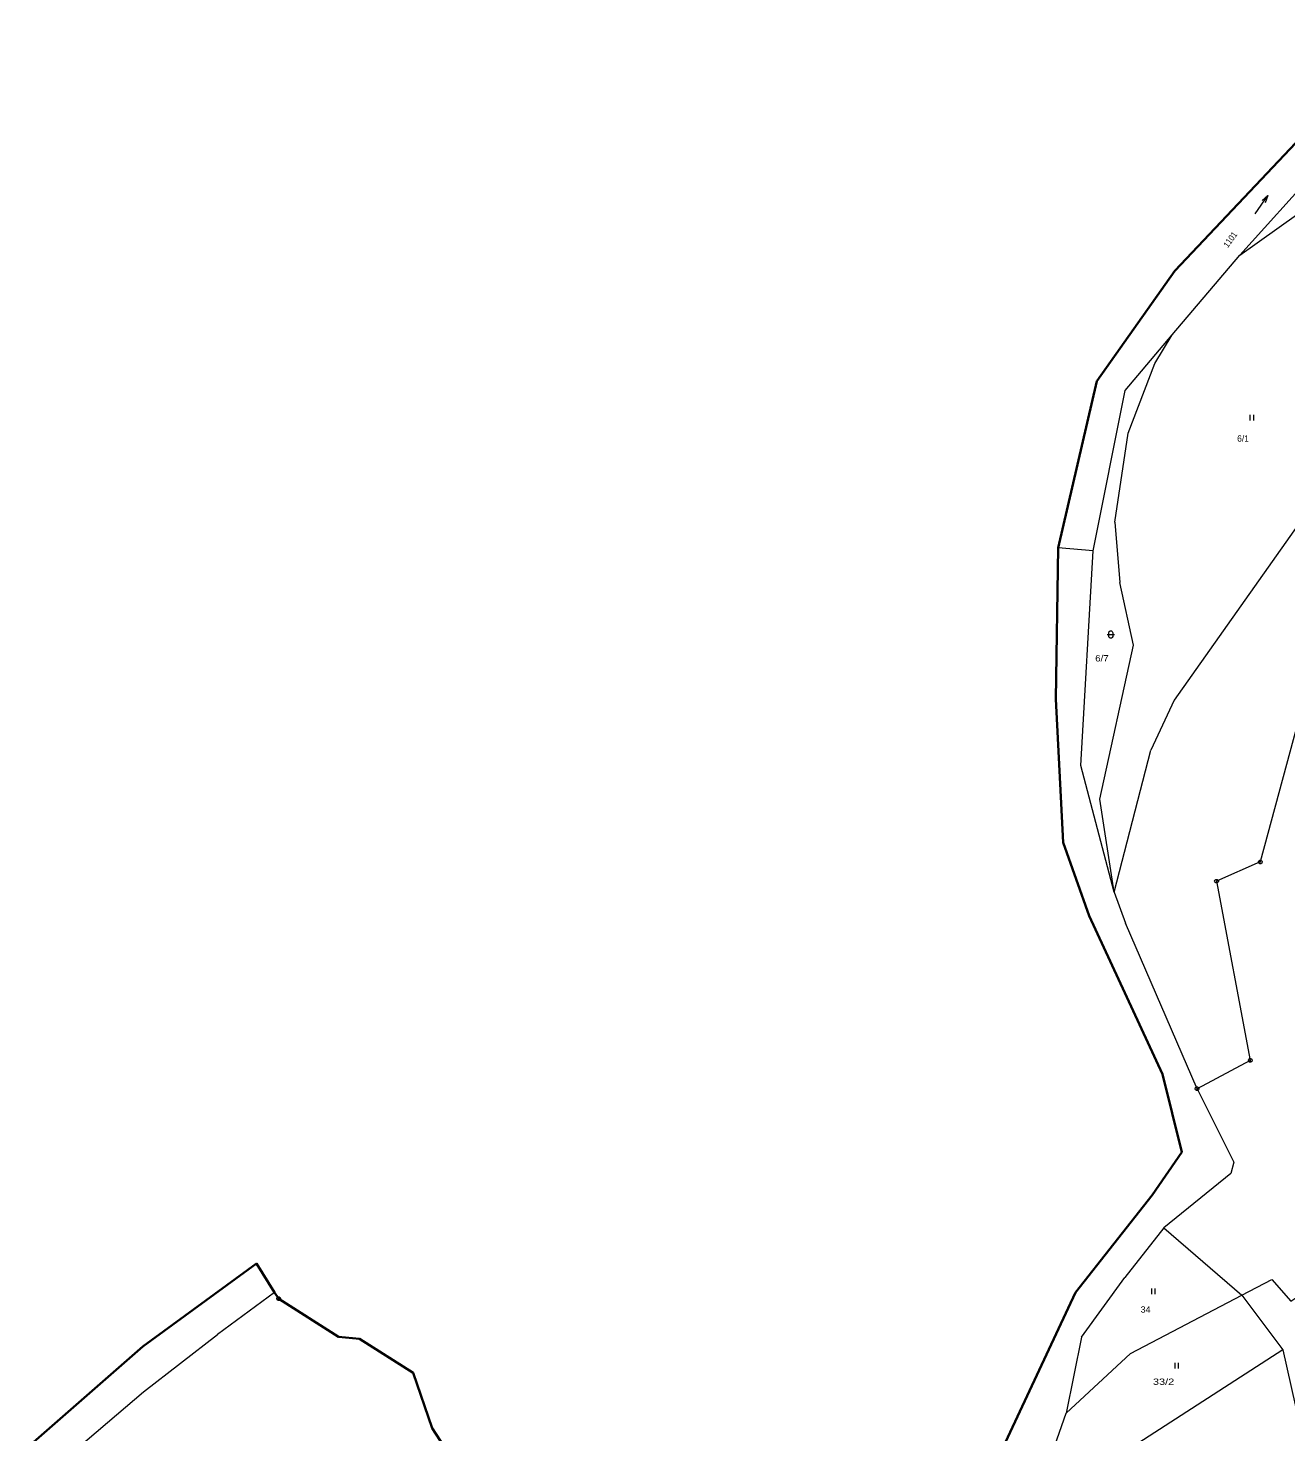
# Model space of a CAD drawing. Extents: x -687390 to -684106, y -954833 to -951648.
# Drawn here: x -687182.1 to -686842.5, y -952373.7 to -951994.7 of the extents above; entities that cross this region are included whole.
import ezdxf

# ---------------------------------------------------------------- set-up
doc = ezdxf.new("R2010")
doc.units = 0
doc.header["$LTSCALE"] = 0.68
for name, color, linetype, lineweight in [('1', 7, 'Continuous', 13), ('3', 7, 'Continuous', 13), ('8', 7, 'Continuous', 13)]:
    doc.layers.add(name, color=color, linetype=linetype, lineweight=lineweight)
doc.layers.add('2', color=7, linetype='Continuous')

msp = doc.modelspace()

# ---------------------------------------------------------------- linework, layer by layer
at = {"layer": '1', "lineweight": 35}
for p, q in [((-686872.53, -952060.23), (-686810.58, -951994.73)), ((-686893.62, -952090.01), (-686872.53, -952060.23)), ((-686904.01, -952134.99), (-686893.62, -952090.01)), ((-686904.01, -952134.99), (-686904.64, -952175.85)), ((-686902.67, -952214.58), (-686904.64, -952175.85)), ((-687098.29, -952347.95), (-687114.45, -952337.69)), ((-687151.09, -952350.57), (-687182.11, -952377.71))]:
    msp.add_line(p, q, dxfattribs=at)
at = {"layer": '1'}
for p, q in [((-686854.94, -952056.03), (-686813.73, -952010.22)), ((-686873.23, -952077.54), (-686854.94, -952056.03)), ((-686888.74, -952128.08), (-686887.36, -952144.36)), ((-686894.58, -952135.87), (-686904.01, -952134.99)), ((-686883.66, -952161.28), (-686887.36, -952144.36)), ((-686888.93, -952227.94), (-686879.03, -952189.6)), ((-686888.93, -952227.94), (-686885.86, -952236.37)), ((-686866.54, -952281.02), (-686885.86, -952236.37)), ((-686875.46, -952318.53), (-686885.99, -952332.01)), ((-686897.74, -952348.12), (-686885.99, -952332.01)), ((-687115.6, -952335.99), (-687130.95, -952347.37)), ((-686884.52, -952352.47), (-686854.46, -952336.7)), ((-687150.92, -952362.86), (-687130.95, -952347.37)), ((-686897.74, -952348.12), (-686901.87, -952368.61)), ((-686843.35, -952351.48), (-686834.2, -952392.4)), ((-686901.87, -952368.61), (-686884.52, -952352.47)), ((-687174.29, -952382.64), (-687150.92, -952362.86))]:
    msp.add_line(p, q, dxfattribs=at)
for points in [[(-686854.94, -952056.03), (-686814.36, -952027.14), (-686800.46, -951995.35)], [(-686888.93, -952227.94), (-686897.92, -952193.73), (-686894.58, -952135.87), (-686885.97, -952092.52), (-686873.23, -952077.54)], [(-686888.74, -952128.08), (-686885.15, -952104.04), (-686877.93, -952085.31), (-686873.23, -952077.54)], [(-686798.99, -952084.75), (-686803.69, -952093.23), (-686810.2, -952100.56), (-686819.98, -952104.32), (-686828.22, -952113.25), (-686872.69, -952176.15), (-686879.03, -952189.6)], [(-686791.07, -952140.62), (-686839.43, -952182.55), (-686849.46, -952219.82), (-686861.27, -952225.02), (-686852.17, -952273.36), (-686866.54, -952281.02)], [(-686888.93, -952227.94), (-686892.78, -952202.83), (-686883.66, -952161.28)], [(-686866.54, -952281.02), (-686856.6, -952300.81), (-686857.44, -952303.87), (-686875.46, -952318.53), (-686854.46, -952336.7), (-686846.31, -952332.52), (-686841.22, -952338.37), (-686831.5, -952331.87), (-686827.68, -952342.74), (-686772.24, -952340.34), (-686749.44, -952344.82), (-686720.16, -952342.03), (-686723.22, -952370.73)], [(-686854.46, -952336.7), (-686843.35, -952351.48), (-686911.22, -952395.33), (-686901.87, -952368.61)]]:
    msp.add_lwpolyline(points, dxfattribs=at)
at = {"layer": '1', "lineweight": 35}
for points in [[(-686938.29, -952406.07), (-686927.39, -952396.02), (-686899.38, -952336.06), (-686889.03, -952322.89), (-686878.68, -952309.72), (-686870.68, -952298.15), (-686875.89, -952277.07), (-686895.7, -952234.39), (-686902.67, -952214.58)], [(-687151.09, -952350.57), (-687120.48, -952328.22), (-687115.6, -952335.99), (-687114.45, -952337.69)], [(-687098.29, -952347.95), (-687092.6, -952348.56), (-687078.11, -952357.72), (-687073.06, -952372.61), (-687064.2, -952386.23), (-687053.17, -952390.55), (-687043.01, -952392.96)]]:
    msp.add_lwpolyline(points, dxfattribs=at)
at = {"layer": '3'}
for p, q in [((-686850.811, -952044.898), (-686847.429, -952039.942)), ((-686852.24, -952099.12), (-686852.24, -952100.62)), ((-686851.24, -952100.62), (-686851.24, -952099.12)), ((-686878.87, -952334.95), (-686878.87, -952336.45)), ((-686877.87, -952336.45), (-686877.87, -952334.95)), ((-686872.55, -952355.03), (-686872.55, -952356.53)), ((-686871.55, -952356.53), (-686871.55, -952355.03))]:
    msp.add_line(p, q, dxfattribs=at)
for points in [[(-686848.969, -952041.312), (-686847.429, -952039.942), (-686848.143, -952041.876)], [(-686890.82, -952158.43), (-686889.55, -952158.43), (-686888.82, -952158.43)]]:
    msp.add_lwpolyline(points, dxfattribs=at)
msp.add_lwpolyline([(-686890.32, -952157.93), (-686890.22, -952157.64), (-686889.97, -952157.46), (-686889.66, -952157.46), (-686889.41, -952157.64), (-686889.31, -952157.93), (-686889.31, -952158.93), (-686889.41, -952159.22), (-686889.66, -952159.4), (-686889.97, -952159.4), (-686890.22, -952159.22), (-686890.32, -952158.93)], close=True, dxfattribs=at)
at = {"layer": '8'}
for p, q in [((-686849.58, -952219.82), (-686849.34, -952219.82)), ((-686861.39, -952225.02), (-686861.15, -952225.02)), ((-686852.29, -952273.36), (-686852.05, -952273.36)), ((-686866.66, -952281.02), (-686866.42, -952281.02)), ((-687114.57, -952337.69), (-687114.33, -952337.69))]:
    msp.add_line(p, q, dxfattribs=at)
for points in [[(-686849.31, -952219.34), (-686849.06, -952219.52), (-686848.96, -952219.81), (-686849.06, -952220.1), (-686849.31, -952220.28), (-686849.62, -952220.28), (-686849.87, -952220.1), (-686849.97, -952219.81), (-686849.87, -952219.52), (-686849.62, -952219.34)], [(-686861.12, -952224.54), (-686860.87, -952224.72), (-686860.77, -952225.01), (-686860.87, -952225.3), (-686861.12, -952225.48), (-686861.43, -952225.48), (-686861.68, -952225.3), (-686861.78, -952225.01), (-686861.68, -952224.72), (-686861.43, -952224.54)], [(-686852.02, -952272.88), (-686851.77, -952273.06), (-686851.67, -952273.35), (-686851.77, -952273.64), (-686852.02, -952273.82), (-686852.33, -952273.82), (-686852.58, -952273.64), (-686852.68, -952273.35), (-686852.58, -952273.06), (-686852.33, -952272.88)], [(-686866.39, -952280.54), (-686866.14, -952280.72), (-686866.04, -952281.01), (-686866.14, -952281.3), (-686866.39, -952281.48), (-686866.7, -952281.48), (-686866.95, -952281.3), (-686867.05, -952281.01), (-686866.95, -952280.72), (-686866.7, -952280.54)], [(-687114.3, -952337.21), (-687114.05, -952337.39), (-687113.95, -952337.68), (-687114.05, -952337.97), (-687114.3, -952338.15), (-687114.61, -952338.15), (-687114.86, -952337.97), (-687114.96, -952337.68), (-687114.86, -952337.39), (-687114.61, -952337.21)]]:
    msp.add_lwpolyline(points, close=True, dxfattribs=at)

# ---------------------------------------------------------------- texts
at = {"layer": '2', "width": 0.9}
msp.add_text('1101', height=1.7, rotation=53.858, dxfattribs=at).set_placement((-686858.227, -952054.156))
at = {"layer": '2'}
msp.add_text('6/1', height=1.7, dxfattribs=at).set_placement((-686855.696, -952106.36))
for s, width, p in [('6/7', 1.15, (-686894.026, -952165.69)), ('34', 1.05, (-686881.755, -952341.46)), ('33/2', 1.3, (-686878.445, -952360.95))]:
    msp.add_text(s, height=1.7, dxfattribs=dict(at, width=width)).set_placement(p)

doc.saveas('drawing.dxf')
